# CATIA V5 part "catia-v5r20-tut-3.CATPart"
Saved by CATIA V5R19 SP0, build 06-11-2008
Part number: c03tut3
Bounding box of the stored display mesh (mm): x 0 to 0, y -40 to 40, z -30 to 30
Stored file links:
  D:\Shriniwas\v5_r19\Part files\c02\c03tut3.CATPart
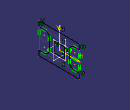
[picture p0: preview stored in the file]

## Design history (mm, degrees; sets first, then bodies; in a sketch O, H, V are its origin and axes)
Body1 (main body)
  Sketch1 on yz-plane, origin (0, 0, 0), H (0, 1, 0), V (0, 0, 1)
    line L1 (-40, -30) -> (40, -30)
    line L2 (40, -30) -> (40, -20)
    line L3 (40, -20) -> (30, -20)
    arc A1 centre (30, -10) radius 10 from (30, -20) to (20, -10) cw
    line L4 (20, -10) -> (20, 10)
    arc A2 centre (30, 10) radius 10 from (20, 10) to (30, 20) cw
    line L5 (30, 20) -> (40, 20)
    point P10 (40, 20)
    line L6 (40, 20) -> (40, 30)
    line L7 (40, 30) -> (-40, 30)
    line L8 (-40, 30) -> (-40, 20)
    point P13 (-40, 20)
    line L9 (-40, 20) -> (-30, 20)
    arc A3 centre (-30, 10) radius 10 from (-30, 20) to (-20, 10) cw
    line L10 (-20, 10) -> (-20, -10)
    arc A4 centre (-30, -10) radius 10 from (-20, -10) to (-30, -20) cw
    line L11 (-30, -20) -> (-40, -20)
    line L12 (-40, -20) -> (-40, -30)
    line L13 (-10, 10) -> (10, 10)
    line L14 (10, 10) -> (10, -10)
    line L15 (10, -10) -> (-10, -10)
    line L16 (-10, -10) -> (-10, 10)
    horizontal: L1 H, L3 H, L7 H, L13 H, L15 H
    vertical: L2 V, L8 V, L14 V, L16 V
    tangency: A1 L2, A1 L3, L4 A1, A2 A1, A2 L4, L5 A2, L6 A2, L9 A2, A3 L8, A3 L9, L10 A3, A4 L3, A4 L10, L11 A4, L12 A3
    coincidence: P10 L2, P13 L5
